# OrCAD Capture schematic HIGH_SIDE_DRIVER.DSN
size A
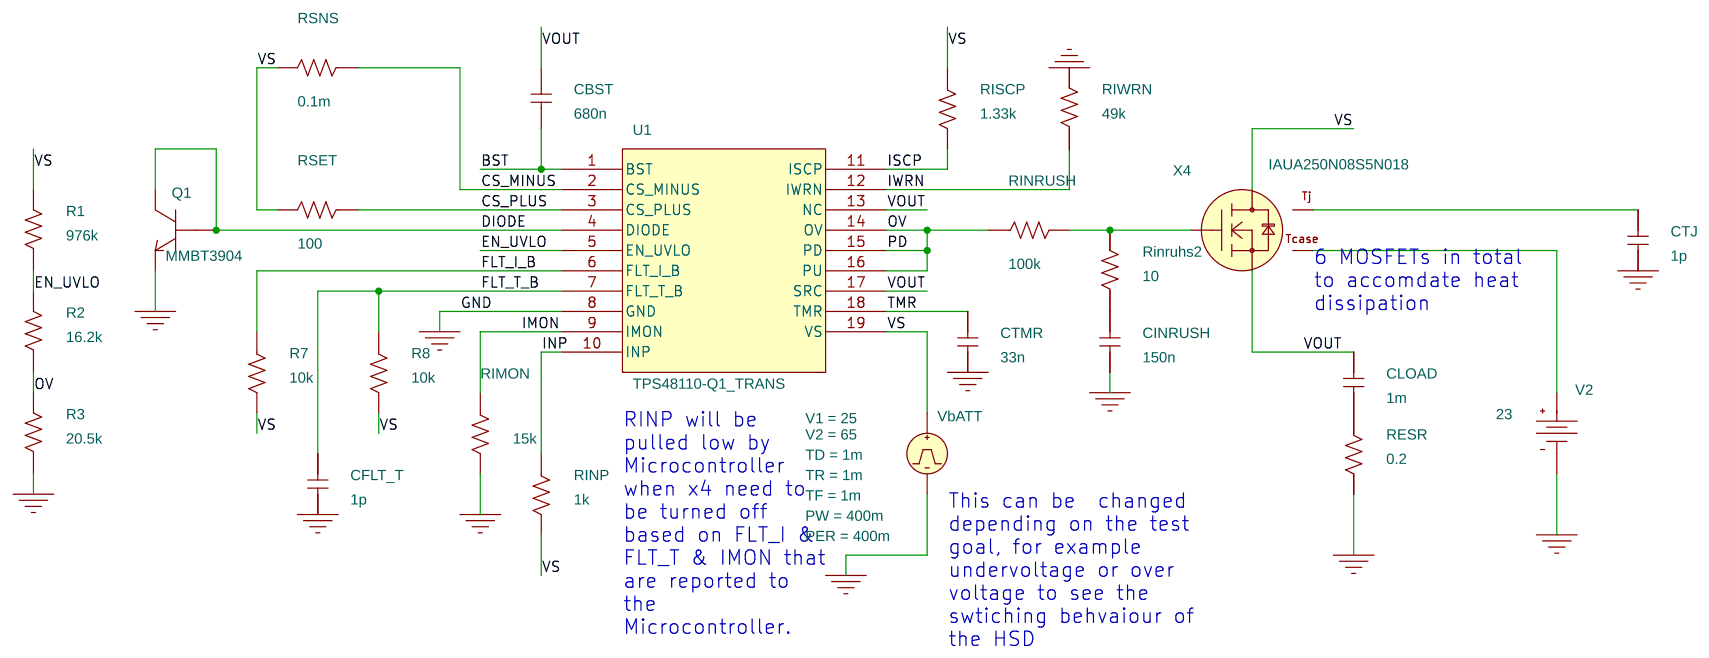
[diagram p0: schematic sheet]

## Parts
CBST  680n  [cap196]
CFLT_T  1p  [cap196]
CINRUSH  150n  [cap196]
CLOAD  1m  [cap196]
CTJ  1p  [cap196]
CTMR  33n  [cap196]
Q1  MMBT3904  [SOT23]
R1  976k  [AXRC05]
R2  16.2k  [AXRC05]
R3  20.5k  [AXRC05]
R7  10k  [AXRC05]
R8  10k  [AXRC05]
RESR  0.2  [AXRC05]
RIMON  15k  [AXRC05]
RINP  1k  [AXRC05]
Rinruhs2  10  [AXRC05]
RINRUSH  100k  [AXRC05]
RISCP  1.33k  [AXRC05]
RIWRN  49k  [AXRC05]
RSET  100  [AXRC05]
RSNS  0.1m  [AXRC05]
U1  TPS48110-Q1_TRANS
V2  VDC
VbATT  VPULSE
X4  IAUA250N08S5N018

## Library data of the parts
CBST = C: VOLTAGE: 50V
CFLT_T CINRUSH CLOAD CTJ CTMR = C
Q1 = MMBT3904
R1-R3 R7 R8 RESR RIMON RINP Rinruhs2 RINRUSH RISCP RIWRN RSET RSNS = R
U1 = TPS48110-Q1_TRANS
V2 = VDC: DC: 23
VbATT = VPULSE: PER: 400m; PW: 400m; TD: 1m; TF: 1m; TR: 1m; V1: 25; V2: 65
X4 = IAUA250N08S5N018

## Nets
0: CFLT_T.1 CINRUSH.1 CTJ.1 CTMR.1 Q1.2(E) R3.1 RESR.2 RIMON.2 RIWRN.2 U1.8(GND) V2.1(-) VbATT.2(-)
BST: CBST.1 U1.1(BST)
CS_MINUS: RSNS.1 U1.2(CS_MINUS)
CS_PLUS: RSET.1 U1.3(CS_PLUS)
DIODE: Q1.1(B) Q1.3(C) U1.4(DIODE)
EN_UVLO: R1.1 R2.2 U1.5(EN_UVLO)
FLT_I_B: R7.1 U1.6(FLT_I_B)
FLT_T_B: CFLT_T.2 R8.1 U1.7(FLT_T_B)
IMON: RIMON.1 U1.9(IMON)
INP: RINP.1 U1.10(INP)
ISCP: RISCP.2 U1.11(ISCP)
IWRN: RIWRN.1 U1.12(IWRN)
OV: R2.1 R3.2 RINRUSH.1 U1.14(OV) U1.15(PD) U1.16(PU)
TMR: CTMR.2 U1.18(TMR)
VOUT: CBST.2 CLOAD.2 U1.13(NC) U1.17(SRC) X4.3(source)
VS: R1.2 R7.2 R8.2 RINP.2 RISCP.1 RSET.2 RSNS.2 U1.19(VS) VbATT.1(+) X4.1(drain)
N03264: V2.0(+) X4.5(Tcase)
N07288: CTJ.2 X4.4(Tj)
N08470: CLOAD.1 RESR.1
N08556: Rinruhs2.2 RINRUSH.2 X4.2(gate)
N08819: CINRUSH.2 Rinruhs2.1

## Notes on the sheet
- 6 MOSFETs in total
  to accomdate heat
  dissipation
- RINP will be
  pulled low by
  Microcontroller
  when x4 need to
  be turned off
  based on FLT_I &
  FLT_T & IMON that
  are reported to
  the
  Microcontroller.
- This can be  changed
  depending on the test
  goal, for example
  undervoltage or over
  voltage to see the
  swtiching behvaiour of
  the HSD
